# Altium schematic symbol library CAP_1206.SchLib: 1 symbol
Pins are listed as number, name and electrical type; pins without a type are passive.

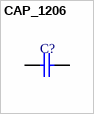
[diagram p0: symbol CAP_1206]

## CAP_1206
designator C?
footprint CAP_1206 (Footprint not found)
pins: 1, 2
